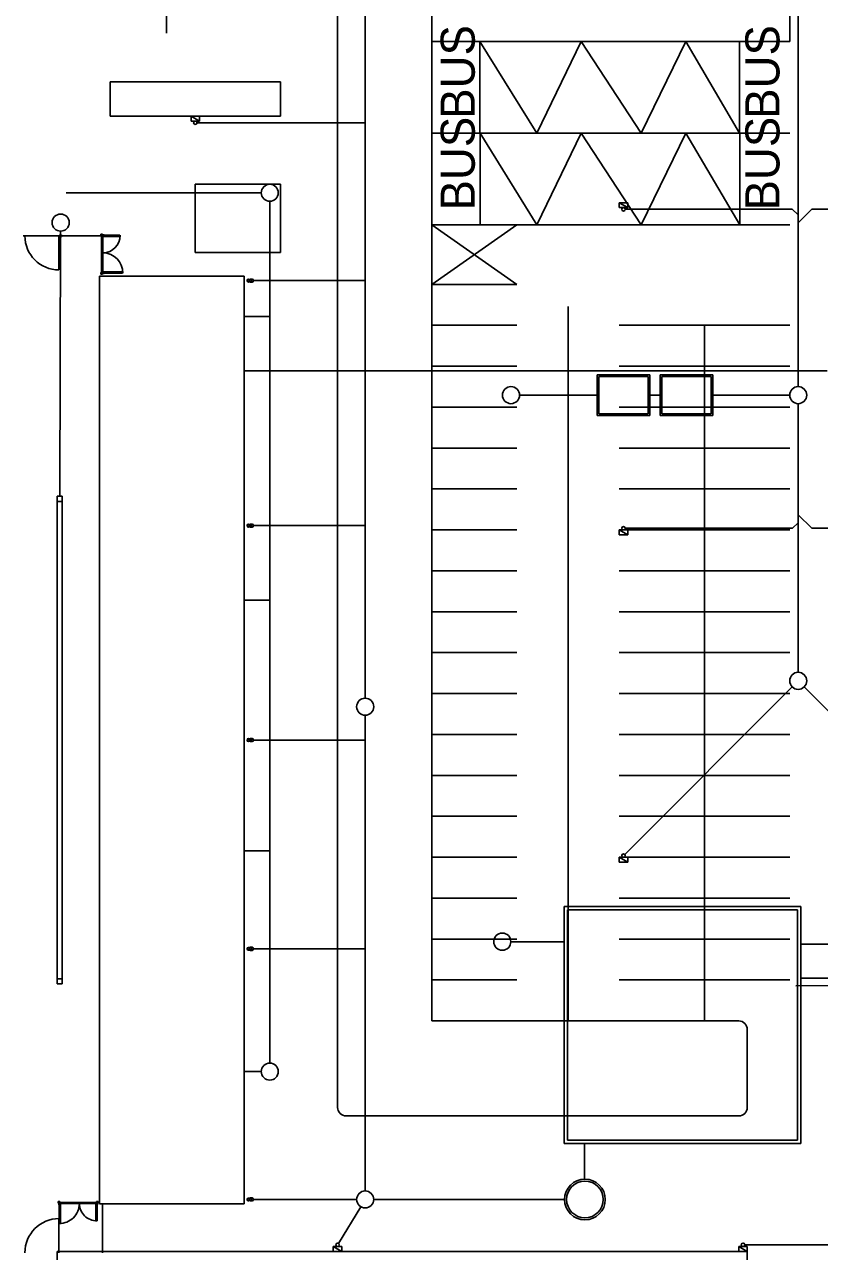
# Model space of a CAD drawing. Extents: x -264205 to -263659, y -1242401 to -1242060.
# Drawn here: x -263972 to -263925.3, y -1242255 to -1242183 of the extents above; entities that cross this region are included whole.
import ezdxf

# ---------------------------------------------------------------- set-up
doc = ezdxf.new("R2010")
doc.units = 0
for name, color, linetype in [('KFA_SO_40-2-II_DAZDOVA_KANALIZACIA', 7, 'Continuous'), ('OBRUBNIKY_KOMUNIKACIE_PROJEKT', 7, 'Continuous'), ('SITUACIA_DSP_2D', 7, 'Continuous'), ('TDZ_VODOROVNE_PROJEKT', 7, 'Continuous')]:
    doc.layers.add(name, color=color, linetype=linetype)

msp = doc.modelspace()

# ---------------------------------------------------------------- linework, layer by layer
at = {"layer": 'KFA_SO_40-2-II_DAZDOVA_KANALIZACIA'}
msp.add_line((-263926.723, -1242239.4), (-263906.731, -1242239.259), dxfattribs=at)
at = {"layer": 'OBRUBNIKY_KOMUNIKACIE_PROJEKT'}
for p, q in [((-263948.093, -1242087.901), (-263948.093, -1242241.458)), ((-263953.617, -1242244.458), (-263953.617, -1242093.307)), ((-263966.968, -1242186.382), (-263956.968, -1242186.382)), ((-263966.968, -1242188.382), (-263966.968, -1242186.382)), ((-263956.968, -1242186.382), (-263956.968, -1242188.382)), ((-263956.968, -1242188.382), (-263966.968, -1242188.382)), ((-263961.968, -1242192.382), (-263956.968, -1242192.382)), ((-263961.968, -1242196.382), (-263961.968, -1242192.382)), ((-263956.968, -1242192.382), (-263956.968, -1242196.382)), ((-263956.968, -1242196.382), (-263961.968, -1242196.382)), ((-263967.597, -1242197.782), (-263959.097, -1242197.782)), ((-263967.597, -1242252.182), (-263967.597, -1242197.782)), ((-263959.097, -1242197.782), (-263959.097, -1242252.182)), ((-263930.08, -1242241.458), (-263948.093, -1242241.458)), ((-263929.582, -1242246.53), (-263929.58, -1242241.959)), ((-263953.617, -1242244.458), (-263953.619, -1242246.529)), ((-263953.119, -1242247.03), (-263930.082, -1242247.03)), ((-263959.097, -1242252.182), (-263967.597, -1242252.182))]:
    msp.add_line(p, q, dxfattribs=at)
for centre, start, end in [((-263930.08, -1242241.958), 359.97854, 89.99994), ((-263953.119, -1242246.53), 179.95255, 270), ((-263930.082, -1242246.53), 270, 359.97854)]:
    msp.add_arc(centre, 0.5, start, end, dxfattribs=at)
at = {"layer": 'SITUACIA_DSP_2D'}
for p, q in [((-263948.093, -1242087.901), (-263948.093, -1242241.458)), ((-263953.617, -1242244.458), (-263953.617, -1242093.307)), ((-263926.593, -1242155.252), (-263926.593, -1242204.252)), ((-263963.661, -1242182), (-263963.661, -1242183.528)), ((-263952, -1242222.527), (-263952, -1242182)), ((-263966.968, -1242186.382), (-263956.968, -1242186.382)), ((-263966.968, -1242188.382), (-263966.968, -1242186.382)), ((-263956.968, -1242186.382), (-263956.968, -1242188.382)), ((-263956.968, -1242188.382), (-263966.968, -1242188.382)), ((-263962.218, -1242188.382), (-263961.718, -1242188.382)), ((-263962.218, -1242188.672), (-263962.218, -1242188.382)), ((-263962.218, -1242188.382), (-263961.718, -1242188.672)), ((-263962.218, -1242188.382), (-263961.718, -1242188.672)), ((-263961.718, -1242188.382), (-263962.218, -1242188.382)), ((-263961.718, -1242188.672), (-263962.218, -1242188.672)), ((-263961.868, -1242188.772), (-263952, -1242188.772)), ((-263961.718, -1242188.382), (-263961.718, -1242188.672)), ((-263961.718, -1242188.672), (-263961.718, -1242188.382)), ((-263961.968, -1242192.382), (-263956.968, -1242192.382)), ((-263961.968, -1242196.382), (-263961.968, -1242192.382)), ((-263956.968, -1242192.382), (-263956.968, -1242196.382)), ((-263958.097, -1242192.883), (-263969.542, -1242192.883)), ((-263957.597, -1242243.932), (-263957.597, -1242193.383)), ((-263937.093, -1242193.752), (-263937.093, -1242193.462)), ((-263937.093, -1242193.462), (-263936.593, -1242193.462)), ((-263936.593, -1242193.752), (-263937.093, -1242193.462)), ((-263936.593, -1242193.752), (-263937.093, -1242193.462)), ((-263937.093, -1242193.462), (-263937.093, -1242193.752)), ((-263936.593, -1242193.752), (-263937.093, -1242193.752)), ((-263937.093, -1242193.752), (-263936.593, -1242193.752)), ((-263936.743, -1242193.852), (-263926.953, -1242193.852)), ((-263936.593, -1242193.462), (-263936.593, -1242193.752)), ((-263926.953, -1242193.852), (-263926.593, -1242194.178)), ((-263925.798, -1242193.852), (-263926.593, -1242194.648)), ((-263920.944, -1242193.852), (-263925.798, -1242193.852)), ((-263969.921, -1242210.683), (-263969.869, -1242195.133)), ((-263967.413, -1242195.307), (-263967.513, -1242195.307)), ((-263967.513, -1242195.307), (-263967.513, -1242195.407)), ((-263967.425, -1242195.32), (-263967.5, -1242195.32)), ((-263967.5, -1242195.32), (-263967.5, -1242195.395)), ((-263967.425, -1242195.395), (-263967.425, -1242195.32)), ((-263967.425, -1242195.395), (-263967.425, -1242195.345)), ((-263967.425, -1242195.345), (-263967.325, -1242195.345)), ((-263967.413, -1242195.407), (-263967.413, -1242195.307)), ((-263967.325, -1242195.345), (-263967.325, -1242195.37)), ((-263972.068, -1242195.407), (-263967.418, -1242195.407)), ((-263969.968, -1242195.407), (-263969.968, -1242197.407)), ((-263967.513, -1242195.407), (-263967.413, -1242195.407)), ((-263967.5, -1242195.395), (-263967.425, -1242195.395)), ((-263967.463, -1242195.407), (-263967.463, -1242196.395)), ((-263967.388, -1242195.407), (-263967.463, -1242195.407)), ((-263967.413, -1242195.357), (-263967.363, -1242195.357)), ((-263967.388, -1242196.395), (-263967.388, -1242195.407)), ((-263967.363, -1242195.457), (-263967.388, -1242195.457)), ((-263966.388, -1242195.371), (-263967.375, -1242195.37)), ((-263967.375, -1242195.37), (-263967.375, -1242195.445)), ((-263967.375, -1242195.445), (-263966.388, -1242195.446)), ((-263967.363, -1242195.357), (-263967.363, -1242195.457)), ((-263967.463, -1242197.557), (-263967.463, -1242196.42)), ((-263967.388, -1242196.42), (-263967.388, -1242197.557)), ((-263956.968, -1242196.382), (-263961.968, -1242196.382)), ((-263967.363, -1242197.507), (-263967.388, -1242197.507)), ((-263967.363, -1242197.607), (-263967.363, -1242197.507)), ((-263967.597, -1242197.782), (-263959.097, -1242197.782)), ((-263967.597, -1242252.182), (-263967.597, -1242197.782)), ((-263967.593, -1242252.182), (-263967.593, -1242197.782)), ((-263967.593, -1242197.782), (-263959.093, -1242197.782)), ((-263967.593, -1242197.782), (-263959.097, -1242197.782)), ((-263967.593, -1242252.182), (-263967.593, -1242197.782)), ((-263967.513, -1242197.557), (-263967.413, -1242197.557)), ((-263967.513, -1242197.657), (-263967.513, -1242197.557)), ((-263967.413, -1242197.657), (-263967.513, -1242197.657)), ((-263967.5, -1242197.57), (-263967.425, -1242197.57)), ((-263967.5, -1242197.645), (-263967.5, -1242197.57)), ((-263967.425, -1242197.645), (-263967.5, -1242197.645)), ((-263967.478, -1242197.782), (-263967.358, -1242197.782)), ((-263967.388, -1242197.557), (-263967.463, -1242197.557)), ((-263967.425, -1242197.57), (-263967.425, -1242197.62)), ((-263967.425, -1242197.57), (-263967.425, -1242197.645)), ((-263967.425, -1242197.62), (-263967.325, -1242197.62)), ((-263967.413, -1242197.557), (-263967.413, -1242197.657)), ((-263967.413, -1242197.607), (-263967.363, -1242197.607)), ((-263967.375, -1242197.52), (-263966.238, -1242197.52)), ((-263967.375, -1242197.595), (-263967.375, -1242197.52)), ((-263966.238, -1242197.595), (-263967.375, -1242197.595)), ((-263967.325, -1242197.62), (-263967.325, -1242197.595)), ((-263959.097, -1242197.782), (-263959.093, -1242252.182)), ((-263959.097, -1242197.782), (-263959.097, -1242252.182)), ((-263959.093, -1242197.782), (-263959.093, -1242252.182)), ((-263958.799, -1242197.962), (-263958.762, -1242197.962)), ((-263958.799, -1242198.102), (-263958.762, -1242198.102)), ((-263958.762, -1242197.962), (-263958.742, -1242197.942)), ((-263958.762, -1242198.102), (-263958.742, -1242198.122)), ((-263958.742, -1242197.942), (-263958.637, -1242197.942)), ((-263958.742, -1242198.122), (-263958.637, -1242198.122)), ((-263958.575, -1242198.032), (-263952, -1242198.032)), ((-263959.097, -1242200.132), (-263957.597, -1242200.132)), ((-263959.097, -1242203.332), (-263958.097, -1242203.332)), ((-263924.893, -1242203.332), (-263958.097, -1242203.332)), ((-263938.393, -1242203.552), (-263935.293, -1242203.552)), ((-263938.393, -1242205.952), (-263938.393, -1242203.552)), ((-263938.293, -1242205.852), (-263938.293, -1242203.652)), ((-263938.293, -1242203.652), (-263935.393, -1242203.652)), ((-263935.393, -1242205.852), (-263935.393, -1242203.652)), ((-263935.293, -1242205.952), (-263935.293, -1242203.552)), ((-263934.693, -1242203.552), (-263931.593, -1242203.552)), ((-263934.693, -1242203.552), (-263934.693, -1242205.952)), ((-263934.593, -1242203.652), (-263934.593, -1242205.852)), ((-263934.593, -1242203.652), (-263931.693, -1242203.652)), ((-263931.693, -1242203.652), (-263931.693, -1242205.852)), ((-263931.593, -1242203.552), (-263931.593, -1242205.952)), ((-263938.393, -1242204.752), (-263942.945, -1242204.752)), ((-263934.693, -1242204.752), (-263935.293, -1242204.752)), ((-263927.093, -1242204.752), (-263931.593, -1242204.752)), ((-263926.593, -1242221.011), (-263926.593, -1242205.252)), ((-263935.293, -1242205.952), (-263938.393, -1242205.952)), ((-263935.393, -1242205.852), (-263938.293, -1242205.852)), ((-263931.593, -1242205.952), (-263934.693, -1242205.952)), ((-263931.693, -1242205.852), (-263934.593, -1242205.852)), ((-263970.071, -1242210.684), (-263969.77, -1242210.682)), ((-263970.07, -1242239.282), (-263970.071, -1242210.684)), ((-263970.071, -1242210.983), (-263969.771, -1242210.985)), ((-263969.77, -1242210.682), (-263969.77, -1242239.282)), ((-263925.798, -1242212.562), (-263926.593, -1242211.767)), ((-263958.799, -1242212.337), (-263958.762, -1242212.337)), ((-263958.799, -1242212.477), (-263958.762, -1242212.477)), ((-263958.762, -1242212.337), (-263958.742, -1242212.317)), ((-263958.762, -1242212.477), (-263958.742, -1242212.497)), ((-263958.742, -1242212.317), (-263958.637, -1242212.317)), ((-263958.742, -1242212.497), (-263958.637, -1242212.497)), ((-263958.575, -1242212.407), (-263952, -1242212.407)), ((-263936.743, -1242212.562), (-263926.919, -1242212.562)), ((-263926.919, -1242212.562), (-263926.593, -1242212.237)), ((-263916.443, -1242212.562), (-263925.798, -1242212.562)), ((-263937.093, -1242212.952), (-263937.093, -1242212.662)), ((-263937.093, -1242212.662), (-263936.593, -1242212.662)), ((-263936.593, -1242212.952), (-263937.093, -1242212.662)), ((-263936.593, -1242212.952), (-263937.093, -1242212.662)), ((-263937.093, -1242212.662), (-263937.093, -1242212.952)), ((-263936.593, -1242212.952), (-263937.093, -1242212.952)), ((-263937.093, -1242212.952), (-263936.593, -1242212.952)), ((-263936.593, -1242212.662), (-263936.593, -1242212.952)), ((-263959.097, -1242216.782), (-263957.597, -1242216.782)), ((-263936.772, -1242231.691), (-263926.947, -1242221.865)), ((-263916.414, -1242231.691), (-263926.24, -1242221.865)), ((-263952, -1242251.432), (-263952, -1242223.527)), ((-263958.799, -1242224.912), (-263958.762, -1242224.912)), ((-263958.799, -1242225.052), (-263958.762, -1242225.052)), ((-263958.762, -1242224.912), (-263958.742, -1242224.892)), ((-263958.762, -1242225.052), (-263958.742, -1242225.072)), ((-263958.742, -1242224.892), (-263958.637, -1242224.892)), ((-263958.742, -1242225.072), (-263958.637, -1242225.072)), ((-263958.575, -1242224.982), (-263952, -1242224.982)), ((-263959.097, -1242231.482), (-263957.597, -1242231.482)), ((-263937.093, -1242231.862), (-263936.593, -1242231.862)), ((-263937.093, -1242232.152), (-263937.093, -1242231.862)), ((-263937.093, -1242231.862), (-263936.593, -1242232.152)), ((-263937.093, -1242231.862), (-263936.593, -1242232.152)), ((-263936.593, -1242231.862), (-263937.093, -1242231.862)), ((-263936.593, -1242231.862), (-263936.593, -1242232.152)), ((-263936.593, -1242232.152), (-263936.593, -1242231.862)), ((-263936.593, -1242232.152), (-263937.093, -1242232.152)), ((-263926.43, -1242234.749), (-263940.33, -1242234.749)), ((-263940.33, -1242234.749), (-263940.33, -1242248.649)), ((-263926.43, -1242248.649), (-263926.43, -1242234.749)), ((-263926.63, -1242234.949), (-263940.13, -1242234.949)), ((-263940.13, -1242234.949), (-263940.13, -1242248.449)), ((-263926.63, -1242248.449), (-263926.63, -1242234.949)), ((-263940.33, -1242236.811), (-263943.454, -1242236.811)), ((-263919.13, -1242236.949), (-263926.43, -1242236.949)), ((-263958.799, -1242237.162), (-263958.762, -1242237.162)), ((-263958.799, -1242237.302), (-263958.762, -1242237.302)), ((-263958.762, -1242237.162), (-263958.742, -1242237.142)), ((-263958.762, -1242237.302), (-263958.742, -1242237.322)), ((-263958.742, -1242237.142), (-263958.637, -1242237.142)), ((-263958.742, -1242237.322), (-263958.637, -1242237.322)), ((-263958.575, -1242237.232), (-263952, -1242237.232)), ((-263969.77, -1242238.982), (-263970.07, -1242238.982)), ((-263907.219, -1242238.949), (-263926.43, -1242238.949)), ((-263969.77, -1242239.282), (-263970.07, -1242239.282)), ((-263930.081, -1242241.458), (-263948.093, -1242241.458)), ((-263929.582, -1242246.53), (-263929.581, -1242241.959)), ((-263959.097, -1242244.432), (-263958.097, -1242244.432)), ((-263953.617, -1242244.458), (-263953.619, -1242246.529)), ((-263953.119, -1242247.03), (-263930.082, -1242247.03)), ((-263940.13, -1242248.449), (-263926.63, -1242248.449)), ((-263940.33, -1242248.649), (-263926.43, -1242248.649)), ((-263939.13, -1242248.649), (-263939.13, -1242250.737)), ((-263970.018, -1242252.152), (-263970.018, -1242252.052)), ((-263970.018, -1242252.052), (-263969.918, -1242252.052)), ((-263969.918, -1242252.152), (-263970.018, -1242252.152)), ((-263970.005, -1242252.14), (-263970.005, -1242252.065)), ((-263970.005, -1242252.065), (-263969.93, -1242252.065)), ((-263969.93, -1242252.14), (-263970.005, -1242252.14)), ((-263969.93, -1242252.14), (-263969.98, -1242252.14)), ((-263969.98, -1242252.14), (-263969.98, -1242252.24)), ((-263969.968, -1242252.152), (-263969.968, -1242252.202)), ((-263969.968, -1242252.202), (-263969.868, -1242252.202)), ((-263969.955, -1242253.327), (-263969.955, -1242252.19)), ((-263969.955, -1242252.19), (-263969.88, -1242252.19)), ((-263969.93, -1242252.065), (-263969.93, -1242252.14)), ((-263969.918, -1242252.052), (-263969.918, -1242252.152)), ((-263969.918, -1242252.102), (-263968.78, -1242252.102)), ((-263969.918, -1242252.177), (-263969.918, -1242252.102)), ((-263968.78, -1242252.177), (-263969.918, -1242252.177)), ((-263969.88, -1242252.19), (-263969.88, -1242253.327)), ((-263969.868, -1242252.202), (-263969.868, -1242252.177)), ((-263968.78, -1242252.102), (-263968.78, -1242252.177)), ((-263967.768, -1242252.102), (-263968.755, -1242252.102)), ((-263968.755, -1242252.102), (-263968.755, -1242252.177)), ((-263968.755, -1242252.177), (-263967.768, -1242252.177)), ((-263967.818, -1242252.202), (-263967.818, -1242252.177)), ((-263967.718, -1242252.202), (-263967.818, -1242252.202)), ((-263967.805, -1242252.19), (-263967.807, -1242253.177)), ((-263967.73, -1242252.19), (-263967.805, -1242252.19)), ((-263967.768, -1242252.152), (-263967.768, -1242252.052)), ((-263967.768, -1242252.052), (-263967.668, -1242252.052)), ((-263967.768, -1242252.177), (-263967.768, -1242252.102)), ((-263967.668, -1242252.152), (-263967.768, -1242252.152)), ((-263967.755, -1242252.14), (-263967.755, -1242252.065)), ((-263967.755, -1242252.065), (-263967.68, -1242252.065)), ((-263967.755, -1242252.14), (-263967.705, -1242252.14)), ((-263967.68, -1242252.14), (-263967.755, -1242252.14)), ((-263967.732, -1242253.177), (-263967.73, -1242252.19)), ((-263967.718, -1242252.152), (-263967.718, -1242252.202)), ((-263967.705, -1242252.14), (-263967.705, -1242252.24)), ((-263967.68, -1242252.065), (-263967.68, -1242252.14)), ((-263967.668, -1242252.052), (-263967.668, -1242252.152)), ((-263959.097, -1242252.182), (-263967.597, -1242252.182)), ((-263959.093, -1242252.182), (-263967.593, -1242252.182)), ((-263959.093, -1242252.182), (-263967.593, -1242252.182)), ((-263967.418, -1242252.182), (-263967.418, -1242255.057)), ((-263958.799, -1242251.862), (-263958.762, -1242251.862)), ((-263958.799, -1242252.002), (-263958.762, -1242252.002)), ((-263958.762, -1242251.862), (-263958.742, -1242251.842)), ((-263958.762, -1242252.002), (-263958.742, -1242252.022)), ((-263958.742, -1242251.842), (-263958.637, -1242251.842)), ((-263958.742, -1242252.022), (-263958.637, -1242252.022)), ((-263958.575, -1242251.932), (-263952.5, -1242251.932)), ((-263940.302, -1242251.932), (-263951.5, -1242251.932)), ((-263969.98, -1242252.24), (-263969.955, -1242252.24)), ((-263967.705, -1242252.24), (-263967.73, -1242252.24)), ((-263953.57, -1242254.506), (-263952.26, -1242252.359)), ((-263969.968, -1242255.057), (-263969.968, -1242253.057)), ((-263929.58, -1242254.982), (-263970.077, -1242254.982)), ((-263970.077, -1242254.982), (-263970.077, -1242263.982)), ((-263953.87, -1242254.692), (-263953.37, -1242254.692)), ((-263953.87, -1242254.982), (-263953.87, -1242254.692)), ((-263953.87, -1242254.692), (-263953.37, -1242254.982)), ((-263953.87, -1242254.692), (-263953.37, -1242254.982)), ((-263953.37, -1242254.692), (-263953.87, -1242254.692)), ((-263953.37, -1242254.982), (-263953.87, -1242254.982)), ((-263953.37, -1242254.692), (-263953.37, -1242254.982)), ((-263953.37, -1242254.982), (-263953.37, -1242254.692)), ((-263930.08, -1242254.692), (-263929.58, -1242254.692)), ((-263930.08, -1242254.982), (-263930.08, -1242254.692)), ((-263930.08, -1242254.692), (-263929.58, -1242254.982)), ((-263930.08, -1242254.692), (-263929.58, -1242254.982)), ((-263929.58, -1242254.692), (-263930.08, -1242254.692)), ((-263929.58, -1242254.982), (-263930.08, -1242254.982)), ((-263929.73, -1242254.592), (-263920.595, -1242254.592)), ((-263929.58, -1242254.692), (-263929.58, -1242254.982)), ((-263929.58, -1242254.982), (-263929.58, -1242254.692)), ((-263929.58, -1242263.982), (-263929.58, -1242254.982))]:
    msp.add_line(p, q, dxfattribs=at)
for centre, radius in [((-263961.968, -1242188.772), 0.1), ((-263957.597, -1242192.883), 0.5), ((-263936.843, -1242193.852), 0.1), ((-263969.868, -1242194.633), 0.5), ((-263969.868, -1242195.407), 0.06), ((-263958.847, -1242198.032), 0.085), ((-263958.847, -1242198.032), 0.0625), ((-263958.637, -1242198.032), 0.0625), ((-263943.445, -1242204.752), 0.5), ((-263926.593, -1242204.752), 0.5), ((-263958.847, -1242212.407), 0.085), ((-263958.847, -1242212.407), 0.0625), ((-263958.637, -1242212.407), 0.0625), ((-263936.843, -1242212.562), 0.1), ((-263926.593, -1242221.511), 0.5), ((-263952, -1242223.027), 0.5), ((-263958.847, -1242224.982), 0.085), ((-263958.847, -1242224.982), 0.0625), ((-263958.637, -1242224.982), 0.0625), ((-263936.843, -1242231.762), 0.1), ((-263943.954, -1242236.811), 0.5), ((-263958.847, -1242237.232), 0.085), ((-263958.847, -1242237.232), 0.0625), ((-263958.637, -1242237.232), 0.0625), ((-263957.597, -1242244.432), 0.5), ((-263939.107, -1242251.932), 1.195), ((-263952, -1242251.932), 0.5), ((-263939.107, -1242251.932), 1.075), ((-263958.847, -1242251.932), 0.085), ((-263958.847, -1242251.932), 0.0625), ((-263958.637, -1242251.932), 0.0625), ((-263953.62, -1242254.592), 0.1), ((-263929.83, -1242254.592), 0.1)]:
    msp.add_circle(centre, radius, dxfattribs=at)
for centre, radius, start, end in [((-263969.968, -1242195.407), 2, 180, 270), ((-263967.4, -1242195.382), 1.025, 270.60954, 0.60953), ((-263967.4, -1242197.582), 1.175, 359.39047, 89.39046), ((-263958.637, -1242198.032), 0.09, 270, 90), ((-263958.637, -1242212.407), 0.09, 270, 90), ((-263958.637, -1242224.982), 0.09, 270, 90), ((-263958.637, -1242237.232), 0.09, 270, 90), ((-263930.081, -1242241.958), 0.5, 359.97854, 89.99994), ((-263953.119, -1242246.53), 0.5, 179.95255, 270), ((-263930.082, -1242246.53), 0.5, 270, 359.97854), ((-263969.943, -1242252.165), 1.175, 269.39046, 359.39047), ((-263967.743, -1242252.165), 1.025, 180.60953, 270.60954), ((-263958.637, -1242251.932), 0.09, 270, 90), ((-263969.968, -1242255.057), 2, 90, 180)]:
    msp.add_arc(centre, radius, start, end, dxfattribs=at)
for centre in [(-263967.4, -1242195.382), (-263967.4, -1242195.382), (-263967.4, -1242197.582), (-263969.943, -1242252.165), (-263969.943, -1242252.165), (-263967.743, -1242252.165)]:
    msp.add_ellipse(centre, major_axis=(0, 0.0125), ratio=0.999995, dxfattribs=at)
at = {"layer": 'TDZ_VODOROVNE_PROJEKT'}
for p, q in [((-263948.093, -1242134.007), (-263948.093, -1242184.007)), ((-263927.093, -1242184.007), (-263927.093, -1242134.007)), ((-263948.093, -1242184.007), (-263927.093, -1242184.007)), ((-263945.265, -1242189.382), (-263945.265, -1242184.007)), ((-263945.265, -1242184.008), (-263941.938, -1242189.382)), ((-263941.938, -1242189.382), (-263939.333, -1242184.008)), ((-263939.333, -1242184.008), (-263935.8, -1242189.382)), ((-263935.8, -1242189.382), (-263933.192, -1242184.008)), ((-263933.192, -1242184.008), (-263930.029, -1242189.382)), ((-263930.029, -1242189.383), (-263930.029, -1242184.008)), ((-263948.093, -1242189.382), (-263927.093, -1242189.382)), ((-263945.263, -1242194.758), (-263945.263, -1242189.383)), ((-263945.263, -1242189.383), (-263941.936, -1242194.758)), ((-263941.936, -1242194.758), (-263939.331, -1242189.383)), ((-263939.331, -1242189.383), (-263935.798, -1242194.758)), ((-263935.798, -1242194.758), (-263933.19, -1242189.383)), ((-263933.19, -1242189.383), (-263930.027, -1242194.758)), ((-263930.027, -1242194.758), (-263930.027, -1242189.383)), ((-263948.093, -1242194.757), (-263927.093, -1242194.757)), ((-263943.093, -1242194.757), (-263948.093, -1242198.257)), ((-263943.093, -1242198.257), (-263948.093, -1242194.757)), ((-263948.093, -1242198.257), (-263943.093, -1242198.257)), ((-263940.088, -1242241.458), (-263940.09, -1242199.557)), ((-263948.093, -1242200.657), (-263943.093, -1242200.657)), ((-263937.093, -1242200.657), (-263932.093, -1242200.657)), ((-263932.093, -1242200.657), (-263932.093, -1242241.457)), ((-263927.093, -1242200.657), (-263932.093, -1242200.657)), ((-263948.093, -1242203.057), (-263943.093, -1242203.057)), ((-263937.093, -1242203.057), (-263932.093, -1242203.057)), ((-263927.093, -1242203.057), (-263932.093, -1242203.057)), ((-263948.093, -1242205.457), (-263943.093, -1242205.457)), ((-263937.093, -1242205.457), (-263932.093, -1242205.457)), ((-263927.093, -1242205.457), (-263932.093, -1242205.457)), ((-263948.093, -1242207.857), (-263943.093, -1242207.857)), ((-263937.093, -1242207.857), (-263932.093, -1242207.857)), ((-263927.093, -1242207.857), (-263932.093, -1242207.857)), ((-263948.093, -1242210.257), (-263943.093, -1242210.257)), ((-263937.093, -1242210.257), (-263932.093, -1242210.257)), ((-263927.093, -1242210.257), (-263932.093, -1242210.257)), ((-263948.093, -1242212.657), (-263943.093, -1242212.657)), ((-263937.093, -1242212.657), (-263932.093, -1242212.657)), ((-263927.093, -1242212.657), (-263932.093, -1242212.657)), ((-263948.093, -1242215.057), (-263943.093, -1242215.057)), ((-263937.093, -1242215.057), (-263932.093, -1242215.057)), ((-263927.093, -1242215.057), (-263932.093, -1242215.057)), ((-263948.093, -1242217.457), (-263943.093, -1242217.457)), ((-263937.093, -1242217.457), (-263932.093, -1242217.457)), ((-263927.093, -1242217.457), (-263932.093, -1242217.457)), ((-263948.093, -1242219.857), (-263943.093, -1242219.857)), ((-263937.093, -1242219.857), (-263932.093, -1242219.857)), ((-263927.093, -1242219.857), (-263932.093, -1242219.857)), ((-263948.093, -1242222.257), (-263943.093, -1242222.257)), ((-263937.093, -1242222.257), (-263932.093, -1242222.257)), ((-263927.093, -1242222.257), (-263932.093, -1242222.257)), ((-263948.093, -1242224.657), (-263943.093, -1242224.657)), ((-263937.093, -1242224.657), (-263932.093, -1242224.657)), ((-263927.093, -1242224.657), (-263932.093, -1242224.657)), ((-263948.093, -1242227.057), (-263943.093, -1242227.057)), ((-263937.093, -1242227.057), (-263932.093, -1242227.057)), ((-263927.093, -1242227.057), (-263932.093, -1242227.057)), ((-263948.093, -1242229.457), (-263943.093, -1242229.457)), ((-263937.093, -1242229.457), (-263932.093, -1242229.457)), ((-263927.093, -1242229.457), (-263932.093, -1242229.457)), ((-263948.093, -1242231.857), (-263943.093, -1242231.857)), ((-263937.093, -1242231.857), (-263932.093, -1242231.857)), ((-263927.093, -1242231.857), (-263932.093, -1242231.857)), ((-263948.093, -1242234.257), (-263943.093, -1242234.257)), ((-263937.093, -1242234.257), (-263932.093, -1242234.257)), ((-263927.093, -1242234.257), (-263932.093, -1242234.257)), ((-263948.093, -1242236.657), (-263943.093, -1242236.657)), ((-263937.093, -1242236.657), (-263932.093, -1242236.657)), ((-263927.093, -1242236.657), (-263932.093, -1242236.657)), ((-263948.093, -1242239.057), (-263943.093, -1242239.057)), ((-263937.093, -1242239.057), (-263932.093, -1242239.057)), ((-263927.093, -1242239.057), (-263932.093, -1242239.057))]:
    msp.add_line(p, q, dxfattribs=at)

# ---------------------------------------------------------------- texts
for p in [(-263945.572, -1242188.544), (-263927.694, -1242188.544), (-263945.57, -1242193.92), (-263927.692, -1242193.92)]:
    msp.add_text('BUS', height=2, rotation=90, dxfattribs=at).set_placement(p)

doc.saveas('drawing.dxf')
